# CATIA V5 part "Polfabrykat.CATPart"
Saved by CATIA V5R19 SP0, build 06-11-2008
Part number: Polfabrykat
Bounding box of the stored display mesh (mm): x -69.908 to 70, y -69.981 to 69.981, z -35.352 to 40.648
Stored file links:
  D:\POBO\podręcznik\ProcesTechnologiczny\Toczenie-CD\Polfabrykat.CATPart
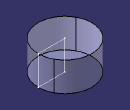
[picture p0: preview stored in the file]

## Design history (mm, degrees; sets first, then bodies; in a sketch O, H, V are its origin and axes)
Body1 "Polfabrykat" (main body)
  Sketch1 on zx-plane, origin (0, 0, 0), H (-1, 0, 0), V (0, 0, 1)
    point P1 (0, 40.6477)
    line L1 (0, 40.6477) -> (-70, 40.6477)
    line L2 (-70, 40.6477) -> (-70, -35.3523)
    line L3 (-70, -35.3523) -> (0, -35.3523)
    line L4 (0, -35.3523) -> (0, 40.6477)
    length L3 = 70
    length L4 = 76
    coincidence: P1 V
    horizontal: L1 H, L3 H
    vertical: L2 V, L4 V
  Shaft1: profile Sketch1, axis Sketch1.L4, angle 360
